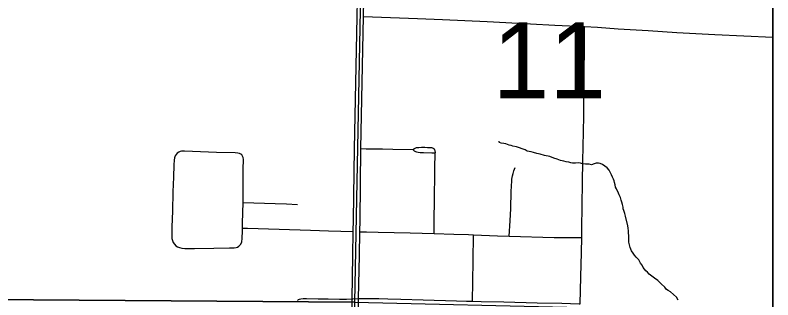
# Model space of a CAD drawing. Extents: x 2.4 to 73.1, y 4.5 to 25.6.
# Drawn here: x 35.8804 to 36.2974, y 23.0807 to 23.2374 of the extents above; entities that cross this region are included whole.
import ezdxf

# ---------------------------------------------------------------- set-up
doc = ezdxf.new("R2010")
doc.units = 0
for name, color, linetype in [('GM_X_City_Street', 7, 'Continuous'), ('GM_X_Corporation', 7, 'Continuous'), ('GM_X_Minor_River', 7, 'Continuous'), ('GM_X_Section', 7, 'Continuous'), ('GM_X_Section_Text', 7, 'Continuous'), ('GM_X_State_Route', 7, 'Continuous'), ('GM_X_US_Shield', 7, 'Continuous'), ('SH_Cut_Line', 7, 'Continuous'), ('SH_Data', 7, 'Continuous')]:
    doc.layers.add(name, color=color, linetype=linetype)

msp = doc.modelspace()

# ---------------------------------------------------------------- linework, layer by layer
at = {"layer": 'GM_X_City_Street'}
for points in [[(36.07216, 23.23665), (36.07699, 23.23646), (36.10189, 23.23553), (36.11554, 23.235), (36.14008, 23.23385), (36.16399, 23.23269), (36.17733, 23.23194), (36.19374, 23.2312)], [(36.19138, 23.07855), (36.1917, 23.09333), (36.19202, 23.10669), (36.19218, 23.11496), (36.19227, 23.11975), (36.1927, 23.14555), (36.19285, 23.15705), (36.19309, 23.17321), (36.19334, 23.18192), (36.19353, 23.20429), (36.1938, 23.22046), (36.19375, 23.23001), (36.19374, 23.2312)], [(36.19374, 23.2312), (36.20081, 23.23073), (36.21228, 23.22993), (36.22869, 23.22891), (36.24457, 23.22789), (36.26537, 23.22672), (36.29738, 23.22522)], [(36.07072, 23.16395), (36.07353, 23.16392), (36.08257, 23.16381), (36.08826, 23.16367), (36.0992, 23.16354)], [(36.0992, 23.16354), (36.10011, 23.16408), (36.10131, 23.1645), (36.10255, 23.16465), (36.10397, 23.16474), (36.10585, 23.16469), (36.10725, 23.16464), (36.10877, 23.1646), (36.10967, 23.16449), (36.10996, 23.16437), (36.11039, 23.16419), (36.11071, 23.16396), (36.11095, 23.16375), (36.1112, 23.16336), (36.11135, 23.16287), (36.11147, 23.1617)], [(36.0992, 23.16354), (36.10005, 23.16281), (36.10074, 23.16232), (36.10124, 23.16218), (36.10213, 23.16196), (36.10326, 23.16185), (36.10514, 23.16175), (36.10962, 23.16168), (36.11147, 23.1617)], [(36.0058, 23.13438), (36.00581, 23.14703), (36.00587, 23.15264), (36.00603, 23.1579), (36.00589, 23.15904), (36.00559, 23.15981), (36.00512, 23.16044), (36.00451, 23.16093), (36.00378, 23.16127), (36.00295, 23.16149), (36.00146, 23.16162), (35.99119, 23.16189), (35.9735, 23.16262), (35.97201, 23.16253), (35.97117, 23.16234), (35.97039, 23.16201), (35.96948, 23.16136), (35.96894, 23.16075), (35.96851, 23.16003), (35.9681, 23.15896), (35.96784, 23.15751), (35.96772, 23.15505), (35.96755, 23.1482), (35.96714, 23.14014), (35.96691, 23.12957), (35.96656, 23.12088), (35.96653, 23.11624), (35.96666, 23.11443), (35.96691, 23.11329), (35.96736, 23.11223), (35.968, 23.11129), (35.96883, 23.11051), (35.9698, 23.1099), (35.97088, 23.10948), (35.97203, 23.10922), (35.97384, 23.10906), (35.9791, 23.10905), (35.98967, 23.10913), (35.99838, 23.10929), (36.00084, 23.10932), (36.00198, 23.10948), (36.00277, 23.10976), (36.00347, 23.11022), (36.00399, 23.11077), (36.00458, 23.11135), (36.00507, 23.11259), (36.0054, 23.11456), (36.00547, 23.11861), (36.00551, 23.1202)], [(36.11094, 23.11731), (36.11094, 23.11799), (36.11096, 23.12641), (36.11114, 23.13385), (36.11144, 23.15309), (36.11147, 23.1617)], [(36.15226, 23.11582), (36.1529, 23.12411), (36.15323, 23.131), (36.15339, 23.14036), (36.15371, 23.14627), (36.1538, 23.14714), (36.15389, 23.14801), (36.15411, 23.14903), (36.15439, 23.15027), (36.15486, 23.15173), (36.15513, 23.15257), (36.15553, 23.15347)], [(36.00551, 23.1202), (36.00555, 23.12286), (36.0058, 23.13438)], [(36.0058, 23.13438), (36.02346, 23.13376), (36.02965, 23.13349), (36.03584, 23.13316)], [(36.00551, 23.1202), (36.0083, 23.12011), (36.02566, 23.11954), (36.04296, 23.11897), (36.05289, 23.11863), (36.06645, 23.11825)], [(36.07017, 23.11814), (36.07373, 23.11807), (36.08013, 23.11795), (36.09772, 23.11751), (36.11094, 23.11731), (36.12187, 23.11686), (36.12995, 23.1166), (36.13272, 23.1165), (36.14576, 23.11601), (36.15226, 23.11582), (36.1771, 23.11511), (36.18611, 23.115), (36.19062, 23.11497), (36.19218, 23.11496)], [(36.13199, 23.07994), (36.132, 23.08055), (36.13218, 23.09003), (36.13271, 23.11581), (36.13272, 23.1165)], [(36.03573, 23.08038), (36.03641, 23.08084), (36.03695, 23.08104), (36.0376, 23.08119), (36.03898, 23.08139), (36.04071, 23.08151), (36.04711, 23.08134), (36.05257, 23.08119), (36.05882, 23.08107), (36.06274, 23.08117), (36.0658, 23.08126), (36.06629, 23.08127), (36.0693, 23.08145)], [(36.0693, 23.08145), (36.07538, 23.08152), (36.0772, 23.08148), (36.0805, 23.08142), (36.08554, 23.08131), (36.09267, 23.08116), (36.10502, 23.08075), (36.12322, 23.0801), (36.12881, 23.07998), (36.13199, 23.07994), (36.13688, 23.07988), (36.1493, 23.07964), (36.16763, 23.07914), (36.18128, 23.07879), (36.19076, 23.07856), (36.19138, 23.07855)]]:
    msp.add_lwpolyline(points, dxfattribs=at)
at = {"layer": 'GM_X_Corporation'}
msp.add_lwpolyline([(36.10545, 21.51712), (36.10544, 21.55708), (36.21546, 21.55504), (36.22306, 21.84551), (36.19174, 21.84592), (36.19241, 21.88501), (36.22325, 21.88487), (36.2575, 21.90719), (36.25749, 21.93181), (36.28758, 21.93095), (36.28806, 21.95216), (36.29738, 21.95194), (36.29738, 23.44254)], dxfattribs=at)
at = {"layer": 'GM_X_Minor_River'}
for points in [[(36.15793, 23.16442), (36.15623, 23.16485), (36.15435, 23.16528), (36.15341, 23.16569), (36.15228, 23.16591), (36.15133, 23.16613), (36.1504, 23.16654), (36.14926, 23.16676), (36.14794, 23.16699), (36.147, 23.1674), (36.14682, 23.16759), (36.14683, 23.16797)], [(36.24532, 23.08055), (36.24441, 23.0821), (36.24275, 23.08367), (36.24108, 23.08505), (36.23978, 23.08584), (36.23884, 23.08644), (36.23793, 23.08761), (36.2359, 23.08957), (36.23405, 23.09133), (36.23219, 23.09272), (36.2307, 23.09371), (36.2294, 23.09489), (36.22848, 23.09586), (36.22756, 23.09665), (36.22682, 23.09762), (36.22609, 23.09859), (36.22537, 23.09975), (36.22445, 23.10092), (36.22355, 23.10266), (36.22208, 23.10422), (36.22116, 23.10539), (36.22043, 23.10636), (36.21952, 23.10772), (36.21881, 23.10945), (36.21848, 23.11098), (36.21814, 23.11251), (36.21818, 23.11384), (36.21821, 23.11479), (36.21806, 23.11612), (36.21791, 23.11745), (36.21794, 23.11878), (36.21779, 23.12012), (36.21764, 23.12145), (36.21628, 23.12682), (36.21594, 23.12816), (36.21542, 23.12988), (36.21507, 23.13084), (36.21491, 23.1318), (36.21457, 23.13314), (36.21422, 23.13448), (36.21388, 23.13563), (36.21354, 23.13697), (36.21282, 23.13851), (36.21247, 23.13947), (36.2114, 23.14178), (36.21086, 23.14275), (36.21052, 23.14409), (36.21017, 23.14524), (36.21001, 23.14619), (36.20966, 23.14715), (36.20912, 23.14831), (36.20858, 23.14946), (36.20805, 23.15062), (36.20733, 23.15216), (36.20623, 23.15333), (36.20493, 23.15432), (36.20362, 23.15512), (36.20231, 23.15573), (36.20137, 23.15594), (36.20023, 23.15598), (36.19908, 23.15563), (36.19754, 23.1551), (36.19622, 23.15533), (36.19432, 23.15539), (36.19262, 23.15563), (36.19149, 23.15585), (36.19035, 23.15607), (36.18883, 23.15593), (36.18712, 23.15597), (36.18618, 23.15619), (36.18505, 23.15641), (36.18372, 23.15664), (36.18241, 23.15706), (36.18052, 23.1575), (36.17864, 23.15812), (36.17676, 23.15874), (36.17469, 23.15956), (36.17167, 23.16022), (36.16941, 23.16086), (36.16753, 23.16129), (36.16564, 23.16173), (36.16432, 23.16214), (36.16319, 23.16237), (36.16225, 23.16258), (36.16112, 23.16319), (36.15943, 23.16381), (36.15793, 23.16442)]]:
    msp.add_lwpolyline(points, dxfattribs=at)
at = {"layer": 'GM_X_Section'}
for points in [[(35.57563, 23.58341), (36.07683, 23.58085), (36.06714, 23.07946), (35.56221, 23.08304)], [(35.56221, 23.08304), (36.06714, 23.07946), (36.0546, 22.56751), (35.55168, 22.57541)]]:
    msp.add_lwpolyline(points, close=True, dxfattribs=at)
at = {"layer": 'GM_X_State_Route'}
for points in [[(36.06656, 23.12475), (36.06722, 23.16376), (36.06866, 23.23645), (36.07093, 23.35596), (36.07227, 23.41895), (36.07243, 23.43363), (36.07251, 23.43853), (36.07267, 23.44651), (36.07299, 23.46452)], [(36.07025, 23.12462), (36.07072, 23.16395), (36.07216, 23.23665), (36.07384, 23.31623)], [(36.06622, 23.10507), (36.06645, 23.11825), (36.06656, 23.12475)], [(36.06986, 23.10508), (36.07017, 23.11814), (36.07025, 23.12462)], [(36.06688, 23.01826), (36.06519, 23.02121), (36.06475, 23.02592), (36.0653, 23.04961), (36.0658, 23.08126), (36.06622, 23.10507)], [(36.06688, 23.01826), (36.0681, 23.02127), (36.06865, 23.02587), (36.06919, 23.04956), (36.0693, 23.08145), (36.06986, 23.10508)]]:
    msp.add_lwpolyline(points, dxfattribs=at)
at = {"layer": 'GM_X_US_Shield'}
msp.add_lwpolyline([(36.29738, 23.07038), (36.29738, 23.57095), (36.07683, 23.58085), (36.06714, 23.07946), (36.19177, 23.07657)], close=True, dxfattribs=at)
at = {"layer": 'SH_Cut_Line'}
msp.add_lwpolyline([(36.29738, 20.02567), (36.29738, 24.78522), (29.49738, 24.78522)], dxfattribs=at)
at = {"layer": 'SH_Data'}
msp.add_lwpolyline([(29.49738, 24.78522), (36.29738, 24.78522), (36.29738, 17.98522), (29.49738, 17.98522)], close=True, dxfattribs=at)

# ---------------------------------------------------------------- texts
at = {"layer": 'GM_X_Section_Text'}
msp.add_text('11', height=0.041856, rotation=0, dxfattribs=at).set_placement((36.14319, 23.1916))

doc.saveas('drawing.dxf')
